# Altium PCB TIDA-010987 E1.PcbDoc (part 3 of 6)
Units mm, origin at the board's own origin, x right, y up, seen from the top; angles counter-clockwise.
Board outline 154.15 x 103.76 mm, 4 copper layers (5V, GND, MidSupply, -5V), stack 1.787 mm thick; 92 components, 52 nets, 1640 pads, 56 vias.
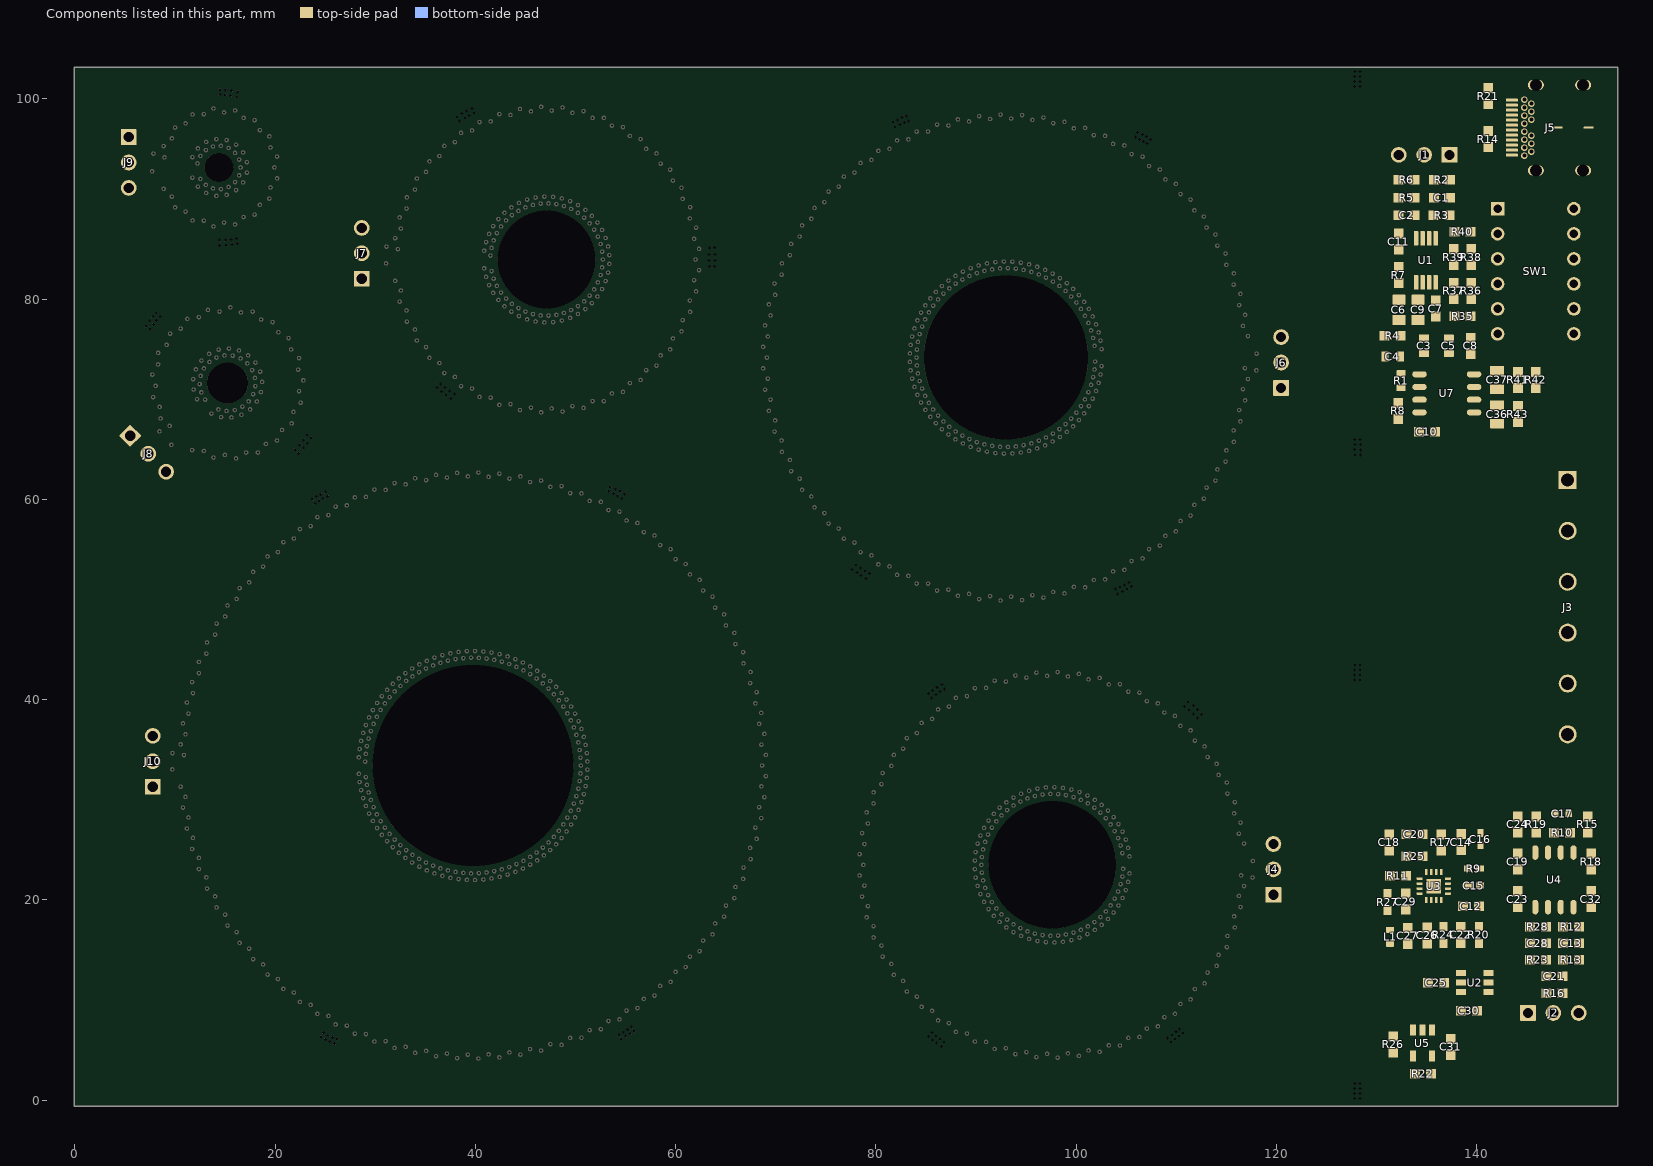
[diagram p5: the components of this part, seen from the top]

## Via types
v1: diameter 0.61, hole 0.203, 5V to -5V, tented both sides, 52 vias
v2: diameter 0.5, hole 0.2, 5V to -5V, tented both sides, 4 vias

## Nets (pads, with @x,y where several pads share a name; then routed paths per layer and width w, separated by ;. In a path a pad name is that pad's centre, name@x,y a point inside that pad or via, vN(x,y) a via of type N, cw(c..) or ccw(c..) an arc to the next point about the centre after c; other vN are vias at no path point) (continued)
copper on no net: (continued)
  5V w0.1: 5.38,66.208 6.209,66.949 8.426,66.825 8.461,66.786 ; 5.383,91.096 5.408,91.905 7.789,94.146 8.547,94.005 cw(c14.398,93.14) 8.883,95.276 ; 5.383,96.176 6.716,96.005 7.858,94.525 ; 7.667,93.134 ccw(c14.398,93.956) 7.724,92.755 ; 7.713,93.14 12.222,93.14 cw(c14.398,93.14) 12.259,93.539 ; 7.744,72.453 ccw(c15.261,71.606) 7.766,70.579 ccw(c7.828,70.199) 7.909,69.823 ccw(c15.261,71.606) 8.402,68.415 cw(c8.573,68.071) 8.913,68.251 12.211,69.994 ; 7.798,31.293 7.745,31.777 9.748,34.271 ; 7.828,70.199 11.872,70.964 ; 7.846,36.244 9.761,34.657 ; 8.086,71.337 12.095,71.487 cw(c12.48,71.501) 12.492,71.886 cw(c15.261,71.606) 12.499,71.948 ccw(c12.573,72.326) 12.698,72.69 cw(c15.261,71.606) 12.905,73.086 ; 8.326,73.464 12.573,72.326 ; 8.327,74.631 12.099,72.985 ; 8.484,69.234 12.634,70.686 ; 8.573,68.071 ccw(c15.261,71.606) 9.311,66.934 8.691,66.477 8.746,63.123 9.127,62.755 ; 8.883,91.003 11.747,92.113 ; 8.962,94.156 11.881,93.61 cw(c12.259,93.539) 12.363,93.91 cw(c14.398,93.14) 12.375,93.942 ccw(c12.548,94.285) 12.779,94.593 cw(c14.398,93.14) 13.087,94.876 ; 9.182,75.426 12.579,73.291 cw(c12.905,73.086) 13.132,73.397 cw(c15.261,71.606) 13.172,73.445 ccw(c13.446,73.715) 13.754,73.945 cw(c15.261,71.606) 14.148,74.156 ; 9.345,65.685 ccw(c14.727,72.14) 9.646,65.446 ; 9.368,65.712 13.293,69.638 cw(c15.261,71.606) 13.022,69.953 ; 9.484,67.342 12.712,69.724 cw(c13.022,69.953) 12.816,70.278 cw(c15.261,71.606) 12.786,70.333 ccw(c12.634,70.686) 12.533,71.057 cw(c15.261,71.606) 12.48,71.501 ; 9.527,76.54 ccw(c15.261,71.606) 8.49,74.98 ccw(c8.327,74.631) 8.183,74.274 ccw(c15.261,71.606) 7.797,72.834 cw(c7.744,72.453) 8.126,72.409 11.833,71.992 ; 9.697,90.228 12.548,91.994 ; 9.696,96.051 12.548,94.285 ; 9.73,33.412 ccw(c39.771,33.873) 9.738,33.027 ; 9.736,33.412 9.743,33.412 29.005,33.412 cw(c39.771,33.412) 29.012,33.801 ; 9.748,34.272 10.517,34.244 cw(c39.771,33.412) 10.582,35.524 ; 10.027,89.155 ccw(c14.398,93.14) 11.423,88.027 ccw(c11.762,87.845) 12.112,87.684 ccw(c14.398,93.14) 13.47,87.298 cw(c13.852,87.25) 13.888,87.633 14.136,90.309 ; 10.027,97.124 12.297,95.055 ; 10.578,77.048 13.446,73.715 ; 10.582,31.301 28.368,32.587 ; 10.81,29.2 ccw(c39.771,33.412) 11.11,27.498 ccw(c11.19,27.121) 11.275,26.746 ccw(c39.771,33.412) 11.611,25.445 cw(c11.718,25.075) 12.087,25.185 28.812,30.155 ; 10.81,37.625 28.457,35.058 ; 10.909,34.455 28.627,33.815 cw(c29.012,33.801) 29.032,34.185 cw(c39.771,33.412) 29.033,34.193 ccw(c29.068,34.576) 29.116,34.958 cw(c39.771,33.412) 29.18,35.346 ; 11.06,30.29 29.068,32.248 ; 11.06,36.535 29.068,34.576 ; 11.066,88.727 12.855,91.096 cw(c13.087,91.403) 12.802,91.661 cw(c14.398,93.14) 12.779,91.686 ccw(c12.548,91.994) 12.375,92.338 cw(c14.398,93.14) 12.259,92.74 8.584,92.053 ccw(c14.398,93.14) 8.755,91.366 ccw(c8.883,91.003) 9.033,90.649 ccw(c14.398,93.14) 9.777,89.447 cw(c10.027,89.155) 10.311,89.414 12.297,91.224 ; 11.066,97.553 12.855,95.183 cw(c13.087,94.876) 13.413,95.08 cw(c14.398,93.14) 13.444,95.095 ccw(c13.803,95.232) 14.18,95.305 cw(c14.398,93.14) 14.599,95.306 ; 11.19,27.121 28.605,30.955 ; 11.19,39.703 ccw(c39.771,33.412) 10.868,38.005 ccw(c10.81,37.625) 10.757,37.243 ccw(c39.771,33.412) 10.612,35.908 cw(c10.582,35.524) 10.966,35.496 28.368,34.237 ; 11.236,78.011 13.426,74.527 ; 11.36,28.226 28.801,31.41 cw(c29.18,31.479) 29.117,31.859 cw(c39.771,33.412) 29.116,31.866 ccw(c29.068,32.248) 29.033,32.632 cw(c39.771,33.412) 29.012,33.024 10.525,32.356 ccw(c39.771,33.412) 10.557,31.685 ccw(c10.582,31.301) 10.612,30.917 ccw(c39.771,33.412) 10.758,29.581 cw(c10.81,29.2) 11.191,29.255 28.457,31.767 ; 11.36,38.598 28.801,35.415 cw(c29.18,35.346) 29.256,35.723 cw(c39.771,33.412) 29.257,35.73 ccw(c29.347,36.105) 29.45,36.476 cw(c39.771,33.412) 29.568,36.85 ; 11.718,25.075 ccw(c39.771,33.412) 12.259,23.434 ccw(c12.393,23.073) 12.531,22.714 ccw(c39.771,33.412) 13.051,21.475 cw(c13.21,21.124) 13.56,21.286 29.395,28.612 ; 11.718,41.749 28.812,36.669 ; 11.726,64.917 13.649,68.555 ; 11.747,94.166 9.242,95.137 ccw(c8.883,95.276) 9.033,95.631 cw(c14.398,93.14) 9.777,96.832 cw(c10.027,97.124) 10.295,97.4 cw(c14.398,93.14) 11.762,98.434 ; 11.762,87.845 13.131,90.595 ; 11.808,26.19 29.347,30.72 ; 11.808,40.635 29.347,36.105 ; 12.39,78.186 13.994,74.509 ; 12.393,23.073 29.075,29.373 ; 12.393,43.752 ccw(c39.771,33.412) 11.83,42.118 ccw(c11.718,41.749) 11.611,41.38 ccw(c39.771,33.412) 11.275,40.079 cw(c11.19,39.703) 11.566,39.621 28.605,35.87 ; 12.402,24.191 29.203,29.852 cw(c29.568,29.975) 29.452,30.342 cw(c39.771,33.412) 29.45,30.349 ccw(c29.347,30.72) 29.257,31.094 cw(c39.771,33.412) 29.18,31.479 ; 12.402,42.634 29.203,36.973 cw(c29.568,36.85) 29.698,37.213 cw(c39.771,33.412) 29.7,37.22 ccw(c29.843,37.577) 29.998,37.929 cw(c39.771,33.412) 30.169,38.283 ; 12.646,73.856 9.819,76.289 ccw(c9.527,76.54) 9.786,76.825 cw(c15.261,71.606) 10.916,77.798 cw(c11.236,78.011) 11.568,78.207 cw(c15.261,71.606) 13.303,78.913 ; 12.885,87.821 13.803,91.047 ; 12.885,98.458 13.803,95.232 ; 12.89,64.828 14.342,68.979 ; 13.087,91.403 ccw(c14.398,93.14) 13.444,91.184 ; 13.131,95.684 11.933,98.09 ccw(c11.762,98.434) 12.112,98.595 cw(c14.398,93.14) 13.47,98.981 cw(c13.852,99.029) 14.237,99.052 cw(c14.398,93.14) 16.017,98.829 ; 13.139,22.24 29.843,29.248 ; 13.139,44.585 29.843,37.577 ; 13.21,21.124 ccw(c39.771,33.412) 13.982,19.578 ccw(c14.166,19.24) 14.355,18.904 ccw(c39.771,33.412) 15.048,17.753 cw(c15.256,17.429) 15.578,17.639 30.194,27.168 ; 13.21,45.7 29.395,38.213 ; 13.444,91.184 cw(c13.803,91.047) 14.18,90.974 ccw(c14.398,93.14) 14.214,90.971 ccw(c14.599,90.973) 14.634,90.59 ; 13.852,87.25 ccw(c14.398,93.14) 15.643,87.357 ccw(c16.017,87.45) 16.384,87.568 ccw(c14.398,93.14) 17.648,88.197 cw(c17.963,88.419) 17.731,88.726 16.111,90.871 ; 13.852,99.029 14.136,95.97 ; 13.855,64.172 ccw(c15.261,71.606) 15.725,64.055 ccw(c16.108,64.088) 16.49,64.141 ccw(c15.261,71.606) 17.93,64.527 cw(c18.286,64.672) 18.133,65.025 16.641,68.444 ; 13.995,74.509 cw(c14.148,74.156) 14.511,74.285 cw(c15.261,71.606) 14.571,74.302 ccw(c14.95,74.371) 15.334,74.388 cw(c15.261,71.606) 15.779,74.34 ; 14.015,20.348 29.826,28.368 cw(c30.169,28.542) 30.001,28.888 cw(c39.771,33.412) 29.998,28.895 ccw(c29.843,29.248) 29.7,29.605 cw(c39.771,33.412) 29.568,29.975 ; 14.015,46.477 29.826,38.457 cw(c30.169,38.283) 30.35,38.623 cw(c39.771,33.412) 30.353,38.629 ccw(c30.546,38.963) 30.75,39.289 cw(c39.771,33.412) 30.97,39.614 ; 14.166,19.24 29.768,27.876 ; 14.166,47.585 ccw(c39.771,33.412) 13.374,46.049 ccw(c13.21,45.7) 13.051,45.35 ccw(c39.771,33.412) 12.531,44.111 cw(c12.393,43.752) 12.753,43.616 29.075,37.452 ; 14.368,74.938 13.403,78.541 ccw(c13.303,78.913) 13.678,79.003 cw(c15.261,71.606) 15.159,79.17 cw(c15.544,79.165) 15.928,79.141 cw(c15.261,71.606) 17.76,78.746 ; 14.457,78.74 14.95,74.371 ; 14.599,90.973 ccw(c14.398,93.14) 15.01,91.051 cw(c15.368,91.192) 15.696,91.393 ccw(c14.398,93.14) 15.723,91.413 ccw(c16.006,91.674) 16.29,91.415 18.485,89.414 ; 14.62,68.216 13.926,64.551 ccw(c13.855,64.172) 13.479,64.254 cw(c15.261,71.606) 12.071,64.746 cw(c11.726,64.917) 11.391,65.106 cw(c15.261,71.606) 10.769,65.519 13.609,69.366 ccw(c15.261,71.606) 13.989,69.131 cw(c14.342,68.979) 14.713,68.877 ccw(c15.261,71.606) 14.775,68.865 ccw(c15.157,68.824) 15.143,68.44 14.993,64.431 ; 14.635,90.589 14.908,87.633 ; 14.908,98.646 14.634,95.69 cw(c14.599,95.306) 14.977,95.237 cw(c14.398,93.14) 15.01,95.228 ccw(c15.368,95.087) 15.696,94.886 cw(c14.398,93.14) 16.006,94.606 ; 15.025,18.523 30.546,27.862 ; 15.025,48.302 30.546,38.963 ; 15.157,68.824 ccw(c15.261,71.606) 15.604,68.844 cw(c15.982,68.917) 16.345,69.042 ccw(c15.261,71.606) 16.403,69.067 ccw(c16.742,69.249) 16.947,68.923 ; 15.176,90.405 16.017,87.45 ; 15.176,95.874 15.912,98.458 ccw(c16.017,98.829) 16.384,98.711 cw(c14.398,93.14) 17.648,98.082 cw(c17.963,97.86) 18.262,97.618 cw(c14.398,93.14) 19.427,96.253 ; 15.256,17.429 ccw(c39.771,33.412) 16.242,16.01 ccw(c16.473,15.702) 16.708,15.397 ccw(c39.771,33.412) 17.559,14.358 cw(c17.812,14.067) 18.101,14.321 31.192,25.855 ; 15.256,49.395 30.194,39.656 ; 15.368,95.087 16.863,98.09 ; 15.368,91.192 16.863,88.189 ; 15.39,75.053 15.544,79.165 ; 15.648,68.177 16.108,64.088 ; 15.982,68.917 17.12,64.67 ; 16.006,91.674 ccw(c14.398,93.14) 16.257,92.009 cw(c16.427,92.354) 16.534,92.723 ccw(c14.398,93.14) 16.54,92.757 ccw(c16.574,93.14) 16.959,93.14 19.928,93.14 ; 16.111,95.408 17.963,97.86 ; 16.164,16.776 30.656,26.989 cw(c30.97,27.211) 30.754,27.529 cw(c39.771,33.412) 30.75,27.536 ccw(c30.546,27.862) 30.353,28.195 cw(c39.771,33.412) 30.169,28.542 ; 16.164,50.048 30.656,39.836 cw(c30.97,39.614) 31.198,39.925 cw(c39.771,33.412) 31.202,39.931 ccw(c31.441,40.233) 31.69,40.526 cw(c39.771,33.412) 31.955,40.816 ; 16.29,94.865 cw(c16.006,94.606) 16.239,94.3 cw(c14.398,93.14) 16.257,94.27 ccw(c16.427,93.926) 16.534,93.556 cw(c14.398,93.14) 16.574,93.14 ; 16.291,94.865 18.485,96.865 ; 16.401,74.862 17.633,78.383 ccw(c17.76,78.746) 18.12,78.61 cw(c15.261,71.606) 19.438,77.913 cw(c19.754,77.692) 20.057,77.456 cw(c15.261,71.606) 21.348,76.098 ; 16.427,92.354 19.555,91.142 ; 16.427,93.926 19.555,95.137 ; 16.473,15.702 30.669,26.493 ; 16.473,51.123 ccw(c39.771,33.412) 15.468,49.717 ccw(c15.256,49.395) 15.048,49.072 ccw(c39.771,33.412) 14.355,47.92 cw(c14.166,47.585) 14.503,47.398 29.768,38.949 ; 16.562,74.066 18.616,77.953 ; 16.596,78.66 15.85,74.718 cw(c15.779,74.34) 16.151,74.243 cw(c15.261,71.606) 16.21,74.222 ccw(c16.562,74.066) 16.889,73.863 cw(c15.261,71.606) 17.229,73.573 ; 16.742,69.249 ccw(c15.261,71.606) 17.1,69.517 cw(c17.371,69.79) 17.601,70.098 ccw(c15.261,71.606) 17.634,70.152 ccw(c17.812,70.493) 18.165,70.339 21.842,68.734 ; 16.815,91.643 19.427,90.026 ; 16.815,94.636 19.1,96.051 ; 16.947,68.923 19.081,65.526 ; 17.193,92.617 19.834,92.123 ccw(c20.212,92.053) 20.129,91.677 cw(c14.398,93.14) 19.619,90.359 cw(c19.427,90.026) 19.214,89.705 cw(c14.398,93.14) 17.963,88.419 ; 17.193,93.662 20.212,94.226 ; 17.31,74.381 19.754,77.692 ; 17.371,69.79 20.704,66.922 ; 17.425,15.116 31.441,26.592 ; 17.425,51.708 31.441,40.233 ; 17.512,68.991 20.196,65.871 ; 17.722,72.906 21.609,74.961 ; 17.812,14.067 ccw(c39.771,33.412) 18.992,12.804 ccw(c19.265,12.533) 19.541,12.265 ccw(c39.771,33.412) 20.533,11.359 cw(c20.825,11.108) 21.074,11.401 32.369,24.699 ; 17.812,52.758 31.192,40.97 ; 17.812,70.493 ccw(c15.261,71.606) 17.957,70.916 cw(c18.027,71.294) 18.043,71.678 ccw(c15.261,71.606) 18.041,71.741 ccw(c17.996,72.123) 18.374,72.194 22.316,72.94 ; 17.996,72.123 ccw(c15.261,71.606) 17.878,72.554 cw(c17.722,72.906) 17.519,73.233 ccw(c15.261,71.606) 17.482,73.283 ccw(c17.229,73.573) 17.501,73.845 20.338,76.683 ; 18.027,71.294 22.396,70.802 ; 18.037,73.654 21.038,75.869 ccw(c21.348,76.098) 21.569,75.782 cw(c15.261,71.606) 22.265,74.464 cw(c22.402,74.104) 22.52,73.738 cw(c15.261,71.606) 22.821,71.888 ; 18.182,69.77 21.341,67.786 ccw(c21.667,67.581) 21.454,67.26 cw(c15.261,71.606) 20.481,66.13 cw(c20.196,65.871) 19.898,65.628 cw(c15.261,71.606) 18.286,64.672 ; 18.518,72.745 22.402,74.104 ; 18.594,70.713 22.568,69.648 ; 18.709,71.735 22.436,71.874 ccw(c22.821,71.888) 22.826,71.503 cw(c15.261,71.606) 22.659,70.022 cw(c22.568,69.648) 22.459,69.278 cw(c15.261,71.606) 21.667,67.581 ; 18.804,13.552 31.675,25.744 cw(c31.955,26.009) 31.695,26.293 cw(c39.771,33.412) 31.69,26.298 ccw(c31.441,26.592) 31.202,26.894 cw(c39.771,33.412) 30.97,27.211 ; 18.804,53.273 31.675,41.081 cw(c31.955,40.816) 32.224,41.091 cw(c39.771,33.412) 32.23,41.096 ccw(c32.509,41.361) 32.798,41.615 cw(c39.771,33.412) 33.102,41.864 ; 19.1,96.051 ccw(c19.427,96.253) 19.619,95.92 cw(c14.398,93.14) 20.129,94.602 cw(c20.212,94.226) 20.271,93.846 cw(c14.398,93.14) 20.212,92.053 ; 19.265,12.533 31.76,25.255 ; 19.265,54.292 ccw(c39.771,33.412) 18.068,53.045 ccw(c17.812,52.758) 17.559,52.467 ccw(c39.771,33.412) 16.708,51.428 cw(c16.473,51.123) 16.779,50.89 30.669,40.331 ; 20.292,12.09 32.509,25.464 ; 20.292,54.734 32.509,41.361 ; 20.825,11.108 ccw(c39.771,33.412) 22.175,10.028 ccw(c22.484,9.799) 22.796,9.573 ccw(c39.771,33.412) 23.908,8.819 cw(c24.233,8.613) 24.437,8.939 33.701,23.724 ; 20.825,55.717 32.369,42.126 ; 21.881,10.74 32.863,24.658 cw(c33.102,24.961) 32.804,25.204 cw(c39.771,33.412) 32.798,25.209 ccw(c32.509,25.464) 32.23,25.729 cw(c39.771,33.412) 31.955,26.009 ; 21.881,56.084 32.863,42.166 cw(c33.102,41.864) 33.408,42.097 cw(c39.771,33.412) 33.414,42.102 ccw(c33.729,42.323) 34.051,42.534 cw(c39.771,33.412) 34.388,42.736 ; 22.484,9.799 33.017,24.187 ; 22.484,57.026 ccw(c39.771,33.412) 21.12,55.964 ccw(c20.825,55.717) 20.533,55.466 ccw(c39.771,33.412) 19.541,54.56 cw(c19.265,54.292) 19.535,54.017 31.76,41.569 ; 23.564,9.509 33.729,24.501 ; 23.564,57.316 33.729,42.323 ; 24.233,8.613 ccw(c39.771,33.412) 25.724,7.739 ccw(c26.063,7.556) 26.404,7.378 ccw(c39.771,33.412) 27.613,6.792 cw(c27.964,6.635) 28.119,6.987 35.158,22.951 ; 24.233,58.212 33.701,43.101 ; 25.331,8.402 34.195,23.755 cw(c34.388,24.089) 34.058,24.287 cw(c39.771,33.412) 34.051,24.291 ccw(c33.729,24.501) 33.414,24.723 cw(c39.771,33.412) 33.102,24.961 ; 25.331,58.423 34.195,43.069 cw(c34.388,42.736) 34.724,42.922 cw(c39.771,33.412) 34.731,42.926 ccw(c35.074,43.1) 35.424,43.262 cw(c39.771,33.412) 35.786,43.414 ; 26.063,7.556 34.415,23.311 ; 26.063,59.268 ccw(c39.771,33.412) 24.56,58.414 ccw(c24.233,58.212) 23.908,58.005 ccw(c39.771,33.412) 22.796,57.251 cw(c22.484,57.026) 22.711,56.715 33.017,42.637 ; 27.173,7.425 35.074,23.725 ; 27.173,59.4 35.074,43.1 ; 27.964,6.635 ccw(c39.771,33.412) 29.565,5.984 ccw(c29.927,5.852) 30.291,5.725 ccw(c39.771,33.412) 31.571,5.319 cw(c31.941,5.214) 32.044,5.585 36.712,22.396 ; 27.964,60.19 35.158,43.873 ; 28.661,82.022 31.107,84.841 31.875,84.787 cw(c47.117,83.947) 32.001,86.071 ; 28.832,87.274 31.055,85.222 31.133,85.225 ; 29.081,6.583 35.643,23.053 cw(c35.786,23.411) 35.431,23.56 cw(c39.771,33.412) 35.424,23.563 ccw(c35.074,23.725) 34.731,23.899 cw(c39.771,33.412) 34.388,24.089 ; 29.081,60.241 35.643,43.771 cw(c35.786,43.414) 36.146,43.55 cw(c39.771,33.412) 36.153,43.552 ccw(c36.518,43.675) 36.887,43.785 cw(c39.771,33.412) 37.267,43.883 ; 29.927,5.852 35.925,22.646 ; 29.927,60.972 ccw(c39.771,33.412) 28.317,60.343 ccw(c27.964,60.19) 27.613,60.032 ccw(c39.771,33.412) 26.404,59.446 cw(c26.063,59.268) 26.243,58.928 34.415,43.513 ; 31.045,5.882 36.518,23.15 ; 31.045,60.943 36.518,43.675 ; 31.069,83.947 ccw(c47.117,84.488) 31.087,83.562 ; 31.082,83.947 41.501,83.947 cw(c47.117,83.947) 41.515,84.339 ; 31.941,5.214 ccw(c39.771,33.412) 33.62,4.801 ccw(c33.997,4.723) 34.374,4.649 ccw(c39.771,33.412) 35.7,4.432 cw(c36.082,4.381) 36.13,4.763 38.33,22.071 ; 31.941,61.611 36.712,44.428 ; 32.001,81.823 40.896,83.073 ; 32.273,84.985 41.131,84.366 cw(c41.515,84.339) 41.555,84.722 cw(c47.117,83.947) 41.557,84.736 ccw(c41.624,85.115) 41.717,85.488 cw(c47.117,83.947) 41.84,85.868 ; 32.443,79.739 ccw(c47.117,83.947) 33.02,78.092 ccw(c33.172,77.738) 33.333,77.388 ccw(c47.117,83.947) 33.972,76.187 cw(c34.172,75.858) 34.498,76.062 41.789,80.618 ; 32.443,88.155 41.078,85.679 ; 32.562,80.853 41.624,82.779 ; 32.562,87.041 41.624,85.115 ; 33.054,5.324 37.177,22.567 cw(c37.267,22.942) 36.894,23.038 cw(c39.771,33.412) 36.887,23.04 ccw(c36.518,23.15) 36.153,23.272 cw(c39.771,33.412) 35.786,23.411 ; 33.054,61.5 37.177,44.258 cw(c37.267,43.883) 37.643,43.966 cw(c39.771,33.412) 37.65,43.967 ccw(c38.029,44.036) 38.41,44.092 cw(c39.771,33.412) 38.8,44.134 ; 33.134,78.858 41.478,81.895 cw(c41.84,82.026) 41.721,82.392 cw(c47.117,83.947) 41.717,82.406 ccw(c41.624,82.779) 41.557,83.158 cw(c47.117,83.947) 41.515,83.555 31.889,82.882 ccw(c47.117,83.947) 31.952,82.204 ccw(c32.001,81.823) 32.059,81.442 ccw(c47.117,83.947) 32.342,80.111 cw(c32.443,79.739) 32.813,79.846 41.078,82.215 ; 33.134,89.036 41.478,85.999 cw(c41.84,85.868) 41.984,86.225 cw(c47.117,83.947) 41.99,86.238 ccw(c42.159,86.583) 42.351,86.917 cw(c47.117,83.947) 42.574,87.248 ; 33.172,77.738 41.378,81.392 ; 33.172,90.156 ccw(c47.117,83.947) 32.554,88.523 ccw(c32.443,88.155) 32.342,87.783 ccw(c47.117,83.947) 32.059,86.452 cw(c32.001,86.071) 32.382,86.018 40.896,84.821 ; 33.979,76.961 42.159,81.311 ; 33.979,90.933 42.159,86.583 ; 33.997,4.723 37.515,22.204 ; 33.997,62.102 ccw(c39.771,33.412) 32.313,61.711 ccw(c31.941,61.611) 31.571,61.505 ccw(c39.771,33.412) 30.291,61.099 cw(c29.927,60.972) 30.057,60.61 35.925,44.179 ; 34.172,75.858 ccw(c47.117,83.947) 35.18,74.433 ccw(c35.423,74.135) 35.674,73.843 ccw(c47.117,83.947) 36.62,72.864 cw(c36.903,72.603) 37.16,72.889 42.913,79.278 ; 34.172,92.036 41.789,87.276 ; 35.079,75.201 42.262,80.42 cw(c42.574,80.646) 42.358,80.965 cw(c47.117,83.947) 42.351,80.977 ccw(c42.159,81.311) 41.99,81.656 cw(c47.117,83.947) 41.84,82.026 ; 35.079,92.693 42.262,87.474 cw(c42.574,87.248) 42.811,87.551 cw(c47.117,83.947) 42.82,87.562 ccw(c43.077,87.848) 43.354,88.116 cw(c47.117,83.947) 43.66,88.372 ; 35.098,4.913 38.029,22.788 ; 35.098,61.912 38.029,44.036 ; 35.423,74.135 42.304,79.909 ; 35.423,93.759 ccw(c47.117,83.947) 34.38,92.36 ccw(c34.172,92.036) 33.972,91.707 ccw(c47.117,83.947) 33.333,90.506 cw(c33.172,90.156) 33.523,89.999 41.378,86.502 ; 36.082,4.381 ccw(c39.771,33.412) 37.802,4.214 ccw(c38.186,4.19) 38.571,4.172 ccw(c39.771,33.412) 39.914,4.148 cw(c40.299,4.152) 40.292,4.537 39.977,21.981 ; 36.082,62.444 38.33,44.754 ; 36.413,73.61 43.077,80.046 ; 36.413,94.284 43.077,87.848 ; 36.903,72.603 ccw(c47.117,83.947) 38.264,71.511 ccw(c38.581,71.292) 38.903,71.081 ccw(c47.117,83.947) 40.081,70.4 cw(c40.425,70.227) 40.594,70.573 44.363,78.3 ; 36.903,95.291 42.913,88.616 ; 37.167,4.65 38.765,22.307 cw(c38.8,22.69) 38.417,22.732 cw(c39.771,33.412) 38.41,22.733 ccw(c38.029,22.788) 37.65,22.857 cw(c39.771,33.412) 37.267,22.942 ; 37.167,62.175 38.765,44.518 cw(c38.8,44.134) 39.184,44.162 cw(c39.771,33.412) 39.192,44.163 ccw(c39.576,44.177) 39.961,44.177 cw(c39.771,33.412) 40.354,44.163 ; 37.515,44.62 34.073,61.725 ccw(c33.997,62.102) 34.374,62.176 cw(c39.771,33.412) 35.7,62.393 cw(c36.082,62.444) 36.464,62.49 cw(c39.771,33.412) 38.186,62.634 ; 37.956,72.221 43.423,79.218 cw(c43.66,79.522) 43.365,79.769 cw(c47.117,83.947) 43.354,79.778 ccw(c43.077,80.046) 42.82,80.332 cw(c47.117,83.947) 42.574,80.646 ; 37.956,95.673 43.423,88.676 cw(c43.66,88.372) 43.971,88.599 cw(c47.117,83.947) 43.983,88.607 ccw(c44.309,88.81) 44.649,88.991 cw(c47.117,83.947) 45.013,89.154 ; 38.186,4.19 39.152,21.996 ; 38.581,71.292 43.604,78.739 ; 38.581,96.602 ccw(c47.117,83.947) 37.192,95.545 ccw(c36.903,95.291) 36.62,95.03 ccw(c47.117,83.947) 35.674,94.051 cw(c35.423,93.759) 35.718,93.512 42.304,87.985 ; 38.8,22.69 ccw(c39.771,33.412) 39.192,22.662 cw(c39.576,22.648) 39.961,22.648 ccw(c39.771,33.412) 39.969,22.648 ccw(c40.354,22.662) 40.374,22.278 ; 39.152,44.828 38.207,62.25 ccw(c38.186,62.634) 38.571,62.653 cw(c39.771,33.412) 39.914,62.677 cw(c40.299,62.673) 40.684,62.663 cw(c39.771,33.412) 42.409,62.558 ; 39.249,4.537 39.576,22.648 ; 39.249,62.288 39.576,44.177 ; 39.677,71.061 44.309,79.084 ; 39.677,96.833 44.309,88.81 ; 39.977,44.843 40.299,62.673 ; 40.299,4.152 ccw(c39.771,33.412) 42.025,4.234 ccw(c42.409,4.266) 42.792,4.304 ccw(c39.771,33.412) 44.125,4.473 cw(c44.505,4.533) 44.443,4.913 41.62,22.13 ; 40.354,22.662 ccw(c39.771,33.412) 40.745,22.691 cw(c41.128,22.732) 41.509,22.788 ccw(c39.771,33.412) 41.516,22.789 ccw(c41.895,22.858) 41.971,22.481 45.469,5.1 ; 40.374,22.278 41.334,4.575 ; 40.425,70.227 ccw(c47.117,83.947) 42.035,69.553 ccw(c42.4,69.429) 42.767,69.315 ccw(c47.117,83.947) 44.088,68.986 cw(c44.466,68.914) 44.533,69.293 46.026,77.76 ; 40.425,97.667 44.363,89.594 ; 40.801,22.026 42.409,4.266 ; 40.801,44.799 42.374,62.175 ccw(c42.409,62.558) 42.792,62.521 cw(c39.771,33.412) 44.125,62.352 cw(c44.505,62.292) 44.885,62.227 cw(c39.771,33.412) 46.577,61.875 ; 41.128,22.732 43.411,4.763 ; 41.128,44.092 43.411,62.062 ; 41.334,62.25 40.374,44.547 cw(c40.354,44.163) 40.737,44.135 cw(c39.771,33.412) 40.745,44.134 ccw(c41.128,44.092) 41.509,44.037 cw(c39.771,33.412) 41.895,43.967 ; 41.543,70.151 44.869,78.383 cw(c45.013,78.74) 44.662,78.897 cw(c47.117,83.947) 44.649,78.903 ccw(c44.309,79.084) 43.983,79.287 cw(c47.117,83.947) 43.66,79.522 ; 41.543,97.743 44.869,89.511 cw(c45.013,89.154) 45.375,89.286 cw(c47.117,83.947) 45.388,89.29 ccw(c45.758,89.396) 46.135,89.476 cw(c47.117,83.947) 46.53,89.532 ; 41.62,44.695 44.505,62.292 ; 41.895,22.858 ccw(c39.771,33.412) 42.278,22.942 cw(c42.651,23.039) 43.02,23.148 ccw(c39.771,33.412) 43.027,23.151 ccw(c43.392,23.274) 43.521,22.911 49.485,6.215 ; 42.4,69.429 45.176,77.972 ; 42.4,98.465 ccw(c47.117,83.947) 40.773,97.831 ccw(c40.425,97.667) 40.081,97.494 ccw(c47.117,83.947) 38.903,96.813 cw(c38.581,96.602) 38.796,96.283 43.604,89.155 ; 42.43,22.293 46.577,4.95 ; 42.43,44.532 46.487,61.5 ccw(c46.577,61.875) 46.951,61.783 cw(c39.771,33.412) 48.245,61.423 cw(c48.613,61.31) 48.979,61.191 cw(c39.771,33.412) 50.603,60.599 ; 42.651,23.039 47.497,5.585 ; 42.651,43.786 47.497,61.24 ; 43.225,22.514 48.496,5.882 ccw(c48.613,5.515) 48.245,5.401 cw(c39.771,33.412) 46.951,5.042 cw(c46.577,4.95) 46.202,4.863 cw(c39.771,33.412) 44.505,4.533 ; 43.225,44.311 48.613,61.31 ; 43.392,23.274 ccw(c39.771,33.412) 43.759,23.412 cw(c44.114,23.561) 44.463,23.723 ccw(c39.771,33.412) 44.47,23.726 ccw(c44.814,23.9) 44.994,23.56 53.298,7.897 ; 43.392,43.551 ccw(c39.771,33.412) 43.02,43.676 cw(c42.651,43.786) 42.278,43.882 ccw(c39.771,33.412) 42.271,43.884 ccw(c41.895,43.967) 41.971,44.344 45.469,61.725 ; 43.517,69.509 45.758,78.498 ; 43.517,98.385 45.758,89.396 ; 44.002,22.791 50.603,6.226 ; 44.002,44.033 50.46,60.241 ccw(c50.603,60.599) 50.959,60.454 cw(c39.771,33.412) 52.189,59.912 cw(c52.536,59.746) 52.882,59.576 cw(c39.771,33.412) 54.403,58.757 ; 44.114,23.561 51.422,6.987 ; 44.114,43.263 51.422,59.838 ; 44.466,68.914 ccw(c47.117,83.947) 46.2,68.71 ccw(c46.584,68.691) 46.969,68.683 ccw(c47.117,83.947) 48.329,68.73 cw(c48.713,68.766) 48.672,69.149 47.774,77.699 ; 44.466,98.98 46.026,90.134 ; 44.758,23.125 52.368,7.425 ccw(c52.536,7.078) 52.189,6.913 cw(c39.771,33.412) 50.959,6.371 cw(c50.603,6.226) 50.244,6.086 cw(c39.771,33.412) 48.613,5.515 ; 44.758,43.7 52.536,59.746 ; 44.814,23.9 ccw(c39.771,33.412) 45.157,24.091 cw(c45.487,24.289) 45.809,24.499 ccw(c39.771,33.412) 45.816,24.504 ccw(c46.13,24.725) 46.358,24.415 56.83,10.109 ; 44.814,42.924 ccw(c39.771,33.412) 44.463,43.102 cw(c44.114,43.263) 43.759,43.412 ccw(c39.771,33.412) 43.752,43.415 ccw(c43.392,43.551) 43.521,43.914 49.485,60.61 ; 45.013,78.74 ccw(c47.117,83.947) 45.388,78.604 cw(c45.758,78.498) 46.135,78.418 ccw(c47.117,83.947) 46.149,78.415 ccw(c46.53,78.362) 46.49,77.979 45.562,69.149 ; 45.176,89.922 42.519,98.099 ccw(c42.4,98.465) 42.767,98.579 cw(c47.117,83.947) 44.088,98.908 cw(c44.466,98.98) 44.846,99.042 cw(c47.117,83.947) 46.584,99.203 ; 45.487,23.511 54.403,8.068 ; 45.487,24.289 55.104,8.939 ; 45.487,42.536 55.104,57.886 ; 45.487,43.313 54.211,58.423 ccw(c54.403,58.757) 54.735,58.562 cw(c39.771,33.412) 55.874,57.849 cw(c56.194,57.635) 56.511,57.417 cw(c39.771,33.412) 57.899,56.386 ; 45.562,98.745 46.49,89.915 cw(c46.53,89.532) 46.914,89.559 cw(c47.117,83.947) 46.928,89.559 ccw(c47.313,89.559) 47.697,89.533 cw(c47.117,83.947) 48.092,89.477 ; 46.13,24.725 ccw(c39.771,33.412) 46.443,24.963 cw(c46.74,25.207) 47.029,25.461 ccw(c39.771,33.412) 47.035,25.466 ccw(c47.314,25.731) 47.584,25.457 60.007,12.808 ; 46.13,42.099 ccw(c39.771,33.412) 45.809,42.325 cw(c45.487,42.536) 45.157,42.734 ccw(c39.771,33.412) 45.15,42.738 ccw(c44.814,42.924) 44.994,43.264 53.298,58.928 ; 46.187,23.95 55.978,9.509 ccw(c56.194,9.19) 55.874,8.976 cw(c39.771,33.412) 54.735,8.263 cw(c54.403,8.068) 54.068,7.878 cw(c39.771,33.412) 52.536,7.078 ; 46.187,42.875 56.194,57.635 ; 46.53,78.362 ccw(c47.117,83.947) 46.928,78.335 cw(c47.313,78.335) 47.697,78.361 ccw(c47.117,83.947) 47.711,78.363 ccw(c48.092,78.417) 48.159,78.038 49.701,69.293 ; 46.584,68.691 46.898,77.668 ; 46.74,25.207 58.467,11.401 ; 46.74,41.618 58.467,55.424 ; 46.853,24.437 57.899,10.438 ; 46.853,42.388 57.66,56.084 ccw(c57.899,56.386) 58.199,56.146 cw(c39.771,33.412) 59.223,55.276 cw(c59.509,55.018) 59.792,54.757 cw(c39.771,33.412) 61.017,53.538 ; 46.898,90.226 46.598,98.818 ccw(c46.584,99.203) 46.969,99.211 cw(c47.117,83.947) 48.329,99.164 cw(c48.713,99.128) 49.095,99.083 cw(c47.117,83.947) 50.81,98.759 ; 47.313,78.335 47.636,69.076 ; 47.313,89.559 47.636,98.818 ; 47.314,25.731 ccw(c39.771,33.412) 47.589,26.011 cw(c47.849,26.296) 48.098,26.589 ccw(c39.771,33.412) 48.103,26.595 ccw(c48.341,26.897) 48.648,26.664 62.762,15.935 ; 47.314,41.093 ccw(c39.771,33.412) 47.029,41.363 cw(c46.74,41.618) 46.443,41.862 ccw(c39.771,33.412) 46.437,41.866 ccw(c46.13,42.099) 46.358,42.41 56.83,56.715 ; 47.482,24.972 59.25,12.09 ccw(c59.509,11.806) 59.223,11.548 cw(c39.771,33.412) 58.199,10.679 cw(c57.899,10.438) 57.595,10.202 cw(c39.771,33.412) 56.194,9.19 ; 47.482,41.853 59.509,55.018 ; 47.774,90.195 48.713,99.128 ; 47.849,26.296 61.441,14.321 ; 47.849,40.529 61.441,52.503 ; 48.071,25.55 61.017,13.287 ; 48.071,41.275 60.737,53.273 ccw(c61.017,53.538) 61.28,53.257 cw(c39.771,33.412) 62.168,52.249 cw(c62.414,51.952) 62.656,51.653 cw(c39.771,33.412) 63.693,50.27 ; 48.092,78.417 ccw(c47.117,83.947) 48.482,78.5 cw(c48.852,78.606) 49.214,78.738 ccw(c47.117,83.947) 49.227,78.743 ccw(c49.579,78.9) 49.747,78.554 53.64,70.573 ; 48.341,26.897 ccw(c39.771,33.412) 48.573,27.214 cw(c48.789,27.532) 48.994,27.859 ccw(c39.771,33.412) 48.998,27.865 ccw(c49.19,28.199) 49.527,28.012 65.038,19.426 ; 48.341,39.928 ccw(c39.771,33.412) 48.098,40.236 cw(c47.849,40.529) 47.589,40.813 ccw(c39.771,33.412) 47.584,40.819 ccw(c47.314,41.093) 47.584,41.368 60.007,54.017 ; 48.617,26.169 62.116,15.116 ccw(c62.414,14.872) 62.168,14.576 cw(c39.771,33.412) 61.28,13.568 cw(c61.017,13.287) 60.75,13.009 cw(c39.771,33.412) 59.509,11.806 ; 48.617,40.655 62.414,51.952 ; 48.637,77.851 50.81,69.135 ; 48.637,90.043 50.717,98.385 ccw(c50.81,98.759) 51.182,98.661 cw(c47.117,83.947) 52.477,98.24 cw(c52.835,98.1) 53.19,97.952 cw(c47.117,83.947) 54.75,97.167 ; 48.713,68.766 ccw(c47.117,83.947) 50.435,69.047 ccw(c50.81,69.135) 51.182,69.233 ccw(c47.117,83.947) 52.477,69.654 cw(c52.835,69.794) 52.691,70.15 49.47,78.122 ; 48.789,27.532 63.963,17.639 ; 48.789,39.292 63.963,49.185 ; 48.852,78.606 51.715,69.795 ; 48.852,89.288 51.715,98.099 ; 49.116,26.827 63.693,16.555 ; 49.116,39.998 63.378,50.048 ccw(c63.693,50.27) 63.912,49.954 cw(c39.771,33.412) 64.646,48.829 cw(c64.847,48.5) 65.043,48.169 cw(c39.771,33.412) 65.87,46.651 ; 49.19,28.199 ccw(c39.771,33.412) 49.374,28.545 cw(c49.542,28.892) 49.697,29.244 ccw(c39.771,33.412) 49.7,29.251 ccw(c49.842,29.609) 50.202,29.473 66.788,23.209 ; 49.19,38.626 ccw(c39.771,33.412) 48.994,38.966 cw(c48.789,39.292) 48.573,39.611 ccw(c39.771,33.412) 48.569,39.617 ccw(c48.341,39.928) 48.648,40.161 62.762,50.89 ; 49.47,89.772 52.835,98.1 ; 49.542,28.892 65.981,21.286 ; 49.542,37.933 65.981,45.539 ; 49.567,27.518 64.517,18.523 ccw(c64.847,18.325) 64.646,17.996 cw(c39.771,33.412) 63.912,16.871 cw(c63.693,16.555) 63.469,16.241 cw(c39.771,33.412) 62.414,14.872 ; 49.567,39.307 64.847,48.5 ; 49.579,78.9 ccw(c47.117,83.947) 49.931,79.087 cw(c50.257,79.291) 50.569,79.517 ccw(c47.117,83.947) 50.58,79.526 ccw(c50.875,79.774) 51.132,79.488 57.074,72.889 ; 49.579,88.994 ccw(c47.117,83.947) 49.214,89.156 cw(c48.852,89.288) 48.482,89.394 ccw(c47.117,83.947) 48.469,89.398 ccw(c48.092,89.477) 48.159,89.856 49.701,98.601 ; 49.842,29.609 ccw(c39.771,33.412) 49.974,29.978 cw(c50.091,30.345) 50.194,30.716 ccw(c39.771,33.412) 50.195,30.724 ccw(c50.285,31.098) 50.661,31.015 67.975,27.204 ; 49.842,37.216 ccw(c39.771,33.412) 49.697,37.581 cw(c49.542,37.933) 49.374,38.279 ccw(c39.771,33.412) 49.37,38.286 ccw(c49.19,38.626) 49.527,38.813 65.038,47.398 ; 49.967,28.24 65.87,20.173 ; 49.967,38.584 65.527,46.477 ccw(c65.87,46.651) 66.042,46.307 cw(c39.771,33.412) 66.606,45.088 cw(c66.757,44.733) 66.904,44.377 cw(c39.771,33.412) 67.504,42.757 ; 50.091,30.345 67.454,25.185 ; 50.091,36.479 67.454,41.64 ; 50.257,79.291 55.438,71.611 ; 50.257,88.603 55.438,96.283 ; 50.258,78.506 54.749,70.727 ; 50.258,89.388 54.557,96.833 ccw(c54.749,97.167) 55.08,96.97 cw(c47.117,83.947) 56.209,96.209 cw(c56.515,95.976) 56.815,95.735 cw(c47.117,83.947) 58.098,94.551 ; 50.285,31.098 ccw(c39.771,33.412) 50.362,31.483 cw(c50.425,31.863) 50.473,32.245 ccw(c39.771,33.412) 50.474,32.252 ccw(c50.509,32.635) 50.893,32.608 ; 50.285,35.727 ccw(c39.771,33.412) 50.194,36.108 cw(c50.091,36.479) 49.974,36.846 ccw(c39.771,33.412) 49.972,36.853 ccw(c49.842,37.216) 50.202,37.352 66.788,43.616 ; 50.313,28.99 66.402,22.24 ccw(c66.757,22.091) 66.606,21.737 cw(c39.771,33.412) 66.042,20.518 cw(c65.87,20.173) 65.693,19.831 cw(c39.771,33.412) 64.847,18.325 ; 50.313,37.835 66.757,44.733 ; 50.425,31.863 68.35,29.255 ; 50.425,34.962 68.35,37.569 ; 50.509,32.635 ccw(c39.771,33.412) 50.53,33.027 cw(c50.537,33.412) 50.53,33.797 ccw(c39.771,33.412) 50.529,33.805 ccw(c50.509,34.189) 50.893,34.217 ; 50.509,34.189 ccw(c39.771,33.412) 50.473,34.58 cw(c50.425,34.962) 50.362,35.342 ccw(c39.771,33.412) 50.361,35.349 ccw(c50.285,35.727) 50.661,35.809 67.975,39.621 ; 50.537,33.412 68.651,33.412 ; 50.605,29.762 67.504,24.068 ; 50.605,37.063 67.139,42.634 ccw(c67.504,42.757) 67.624,42.391 cw(c39.771,33.412) 68.007,41.103 cw(c68.106,40.731) 68.2,40.358 cw(c39.771,33.412) 68.56,38.668 ; 50.84,30.553 67.733,26.19 ccw(c68.106,26.093) 68.007,25.721 cw(c39.771,33.412) 67.624,24.434 cw(c67.504,24.068) 67.378,23.704 cw(c39.771,33.412) 66.757,22.091 ; 50.84,36.272 68.106,40.731 ; 50.875,79.774 ccw(c47.117,83.947) 51.161,80.051 cw(c51.419,80.337) 51.656,80.64 ccw(c47.117,83.947) 51.664,80.652 ccw(c51.879,80.971) 52.206,80.767 59.736,76.062 ; 50.875,88.12 ccw(c47.117,83.947) 50.569,88.377 cw(c50.257,88.603) 49.931,88.807 ccw(c47.117,83.947) 49.919,88.814 ccw(c49.579,88.994) 49.747,89.34 53.64,97.321 ; 50.893,32.608 68.575,31.328 ; 50.893,34.217 68.575,35.496 ; 50.985,78.996 56.278,72.221 ccw(c56.515,71.918) 56.209,71.685 cw(c47.117,83.947) 55.08,70.924 cw(c54.749,70.727) 54.414,70.539 cw(c47.117,83.947) 52.835,69.794 ; 50.985,88.898 56.515,95.976 ; 51.018,31.359 68.56,28.157 ; 51.018,35.465 68.181,38.598 ccw(c68.56,38.668) 68.627,38.288 cw(c39.771,33.412) 68.82,36.959 cw(c68.864,36.576) 68.903,36.193 cw(c39.771,33.412) 69.017,34.469 ; 51.136,32.176 68.481,30.29 ccw(c68.864,30.248) 68.82,29.866 cw(c39.771,33.412) 68.627,28.536 cw(c68.56,28.157) 68.488,27.779 cw(c39.771,33.412) 68.106,26.093 ; 51.136,34.648 68.864,36.576 ; 51.196,33 69.017,32.356 ; 51.196,33.825 68.632,34.455 ccw(c69.017,34.469) 69.028,34.084 cw(c39.771,33.412) 69.028,32.741 cw(c69.017,32.356) 69,31.971 cw(c39.771,33.412) 68.864,30.248 ; 51.419,80.337 58.516,74.382 ; 51.419,87.557 58.516,93.512 ; 51.636,79.583 58.098,73.343 ; 51.636,88.311 57.821,94.284 ccw(c58.098,94.551) 58.362,94.271 cw(c47.117,83.947) 59.236,93.228 cw(c59.467,92.92) 59.689,92.605 cw(c47.117,83.947) 60.595,91.113 ; 51.879,80.971 ccw(c47.117,83.947) 52.079,81.317 cw(c52.247,81.663) 52.392,82.02 ccw(c47.117,83.947) 52.396,82.033 ccw(c52.515,82.399) 52.885,82.293 ; 51.879,86.923 ccw(c47.117,83.947) 51.656,87.254 cw(c51.419,87.557) 51.161,87.843 ccw(c47.117,83.947) 51.152,87.853 ccw(c50.875,88.12) 51.132,88.406 57.074,95.005 ; 52.2,80.254 59.155,75.201 ccw(c59.467,74.974) 59.236,74.666 cw(c47.117,83.947) 58.362,73.623 cw(c58.098,73.343) 57.827,73.069 cw(c47.117,83.947) 56.515,71.918 ; 52.2,87.64 59.467,92.92 ; 52.247,81.663 60.711,77.895 ; 52.247,86.231 60.711,89.999 ; 52.515,82.399 ccw(c47.117,83.947) 52.611,82.786 cw(c52.678,83.165) 52.719,83.548 ccw(c47.117,83.947) 52.719,83.562 ccw(c52.733,83.947) 53.118,83.947 61.997,83.947 ; 52.515,85.495 ccw(c47.117,83.947) 52.392,85.874 cw(c52.247,86.231) 52.079,86.577 ccw(c47.117,83.947) 52.072,86.59 ccw(c51.879,86.923) 52.206,87.127 59.736,91.832 ; 52.664,80.998 60.595,76.781 ; 52.664,86.896 60.255,90.933 ccw(c60.595,91.113) 60.772,90.771 cw(c47.117,83.947) 61.325,89.528 cw(c61.461,89.168) 61.589,88.805 cw(c47.117,83.947) 62.048,87.121 ; 52.678,83.165 61.852,81.876 ; 52.678,84.729 61.852,86.018 ; 52.733,83.947 ccw(c47.117,83.947) 52.719,84.346 cw(c52.678,84.729) 52.611,85.108 ccw(c47.117,83.947) 52.608,85.121 ccw(c52.515,85.495) 52.885,85.601 ; 52.885,82.293 61.421,79.846 ; 52.885,85.601 61.421,88.048 ; 53.021,81.798 61.1,78.858 ccw(c61.461,78.726) 61.325,78.366 cw(c47.117,83.947) 60.772,77.123 cw(c60.595,76.781) 60.41,76.443 cw(c47.117,83.947) 59.467,74.974 ; 53.021,86.096 61.461,89.168 ; 53.262,82.641 62.048,80.773 ; 53.262,85.253 61.672,87.041 ccw(c62.048,87.121) 62.124,86.743 cw(c47.117,83.947) 62.313,85.396 cw(c62.345,85.012) 62.367,84.627 cw(c47.117,83.947) 62.345,82.882 ; 53.384,83.509 61.961,82.909 ccw(c62.345,82.882) 62.313,82.498 cw(c47.117,83.947) 62.124,81.151 cw(c62.048,80.773) 61.964,80.398 cw(c47.117,83.947) 61.461,78.726 ; 53.384,84.385 62.345,85.012 ; 68.755,73.079 ccw(c92.996,74.152) 68.897,71.323 ccw(c68.945,70.941) 68.999,70.56 ccw(c92.996,74.152) 69.241,69.204 cw(c69.323,68.828) 69.698,68.912 83.637,72.047 ; 68.755,75.226 83.412,74.577 ; 68.945,70.941 83.487,72.883 ; 68.945,77.364 ccw(c92.996,74.152) 68.775,75.61 ccw(c68.755,75.226) 68.741,74.841 ccw(c92.996,74.152) 68.741,73.464 cw(c68.755,73.079) 69.14,73.096 83.412,73.728 ; 69.116,74.152 84.07,74.152 ; 69.21,72.042 83.721,73.33 cw(c84.105,73.364) 84.079,73.748 cw(c92.996,74.152) 84.078,73.768 ccw(c84.07,74.152) 84.078,74.537 cw(c92.996,74.152) 84.105,74.941 ; 69.21,76.263 83.721,74.975 cw(c84.105,74.941) 84.147,75.324 cw(c92.996,74.152) 84.15,75.344 ccw(c84.209,75.724) 84.285,76.102 cw(c92.996,74.152) 84.382,76.495 ; 69.323,68.828 ccw(c92.996,74.152) 69.772,67.124 ccw(c69.886,66.756) 70.006,66.391 ccw(c92.996,74.152) 70.484,65.099 cw(c70.63,64.743) 70.985,64.892 84.154,70.432 ; 69.323,79.477 83.637,76.258 ; 69.489,69.948 84.209,72.581 ; 69.489,78.357 84.209,75.724 ; 69.886,66.756 83.859,71.228 ; 69.886,81.549 ccw(c92.996,74.152) 69.41,79.852 ccw(c69.323,79.477) 69.241,79.101 ccw(c92.996,74.152) 68.999,77.745 cw(c68.945,77.364) 69.326,77.313 83.487,75.422 ; 69.953,67.887 84.011,71.709 cw(c84.382,71.81) 84.29,72.184 cw(c92.996,74.152) 84.285,72.203 ccw(c84.209,72.581) 84.15,72.961 cw(c92.996,74.152) 84.105,73.364 ; 69.953,80.418 84.011,76.596 cw(c84.382,76.495) 84.491,76.864 cw(c92.996,74.152) 84.498,76.883 ccw(c84.623,77.247) 84.764,77.605 cw(c92.996,74.152) 84.929,77.975 ; 70.597,65.875 84.623,71.058 ; 70.597,82.43 84.623,77.247 ; 70.63,64.743 ccw(c92.996,74.152) 71.372,63.145 ccw(c71.549,62.803) 71.732,62.464 ccw(c92.996,74.152) 72.429,61.277 cw(c72.636,60.952) 72.959,61.161 84.947,68.933 ; 70.63,83.562 84.154,77.873 ; 71.416,63.928 84.582,70.165 cw(c84.929,70.33) 84.772,70.682 cw(c92.996,74.152) 84.764,70.7 ccw(c84.623,71.058) 84.498,71.422 cw(c92.996,74.152) 84.382,71.81 ; 71.416,84.377 84.582,78.14 cw(c84.929,77.975) 85.102,78.319 cw(c92.996,74.152) 85.111,78.337 ccw(c85.299,78.673) 85.501,79 cw(c92.996,74.152) 85.728,79.335 ; 71.549,62.803 84.517,69.665 ; 71.549,85.502 ccw(c92.996,74.152) 70.782,83.916 ccw(c70.63,83.562) 70.484,83.206 ccw(c92.996,74.152) 70.006,81.914 cw(c69.886,81.549) 70.253,81.431 83.859,77.077 ; 72.404,62.06 85.299,69.632 ; 72.404,86.245 85.299,78.673 ; 72.636,60.952 ccw(c92.996,74.152) 73.648,59.509 ccw(c73.883,59.204) 74.122,58.903 ccw(c92.996,74.152) 75.018,57.856 cw(c75.279,57.573) 75.56,57.836 85.991,67.598 ; 72.636,87.353 84.947,79.372 ; 73.554,60.288 85.415,68.746 ; 73.554,88.017 85.415,79.559 ; 73.883,59.204 85.44,68.242 ; 73.883,89.101 ccw(c92.996,74.152) 72.848,87.675 ccw(c72.636,87.353) 72.429,87.028 ccw(c92.996,74.152) 71.732,85.841 cw(c71.549,85.502) 71.89,85.322 84.517,78.64 ; 74.855,58.624 86.215,68.348 ; 74.855,89.681 86.215,79.957 ; 75.279,57.573 ccw(c92.996,74.152) 76.528,56.331 ccw(c76.813,56.072) 77.102,55.818 ccw(c92.996,74.152) 78.168,54.946 cw(c78.474,54.713) 78.705,55.021 87.255,66.467 ; 75.279,90.732 85.991,80.707 ; 76.298,57.081 86.485,67.496 cw(c86.754,67.771) 86.485,68.046 cw(c92.996,74.152) 86.472,68.061 ccw(c86.215,68.348) 85.971,68.645 ; 76.298,91.224 86.485,80.809 cw(c86.754,80.534) 87.035,80.797 cw(c92.996,74.152) 87.05,80.81 ccw(c87.343,81.061) 87.646,81.298 cw(c92.996,74.152) 87.976,81.533 ; 76.813,56.072 86.598,67.004 ; 76.813,92.233 ccw(c92.996,74.152) 75.544,91.011 ccw(c75.279,90.732) 75.018,90.448 ccw(c92.996,74.152) 74.122,89.402 cw(c73.883,89.101) 74.186,88.864 85.44,80.063 ; 77.873,55.672 87.343,67.244 ; 77.873,92.633 87.343,81.061 ; 78.392,22.431 89.886,23.065 ; 78.392,24.554 ccw(c97.628,23.493) 78.375,22.816 ccw(c78.392,22.431) 78.418,22.047 ccw(c97.628,23.493) 78.566,20.702 cw(c78.626,20.322) 79.006,20.385 89.98,22.216 ; 78.474,54.713 ccw(c92.996,74.152) 79.923,53.71 ccw(c80.249,53.505) 80.579,53.306 ccw(c92.996,74.152) 81.781,52.635 cw(c82.124,52.46) 82.296,52.804 88.698,65.576 ; 78.474,93.592 87.255,81.838 ; 78.626,20.322 ccw(c97.628,23.493) 78.989,18.622 ccw(c79.09,18.251) 79.199,17.881 ccw(c97.628,23.493) 79.638,16.601 cw(c79.779,16.243) 80.136,16.388 90.444,20.575 ; 78.626,26.664 89.98,24.769 ; 78.748,23.493 90.156,23.493 cw(c90.541,23.493) 90.551,23.877 cw(c97.628,23.493) 90.552,23.889 ccw(c90.584,24.272) 90.637,24.654 cw(c97.628,23.493) 90.713,25.042 ; 78.863,21.416 90.584,22.713 ; 78.863,25.57 90.584,24.272 ; 79.09,18.251 90.167,21.383 ; 79.09,28.735 ccw(c97.628,23.493) 78.693,27.043 ccw(c78.626,26.664) 78.566,26.283 ccw(c97.628,23.493) 78.418,24.938 cw(c78.392,24.554) 78.777,24.533 89.886,23.92 ; 79.205,19.364 90.337,21.859 cw(c90.713,21.943) 90.639,22.321 cw(c97.628,23.493) 90.637,22.332 ccw(c90.584,22.713) 90.552,23.097 cw(c97.628,23.493) 90.541,23.493 ; 79.205,27.621 90.337,25.127 cw(c90.713,25.042) 90.807,25.416 cw(c97.628,23.493) 90.81,25.427 ccw(c90.925,25.794) 91.06,26.154 cw(c97.628,23.493) 91.219,26.517 ; 79.565,54.408 87.759,66.453 cw(c87.976,66.772) 87.662,66.995 cw(c92.996,74.152) 87.646,67.007 ccw(c87.343,67.244) 87.05,67.494 cw(c92.996,74.152) 86.754,67.771 ; 79.565,93.897 87.759,81.852 cw(c87.976,81.533) 88.298,81.743 cw(c92.996,74.152) 88.315,81.753 ccw(c88.648,81.948) 88.988,82.128 cw(c92.996,74.152) 89.354,82.302 ; 79.771,17.362 90.925,21.191 ; 79.771,29.623 90.925,25.794 ; 79.779,16.243 ccw(c97.628,23.493) 80.505,14.664 ccw(c80.685,14.324) 80.872,13.987 ccw(c97.628,23.493) 81.58,12.834 cw(c81.797,12.515) 82.113,12.735 91.256,19.074 ; 79.779,30.742 90.444,26.411 ; 80.249,53.505 87.957,65.989 ; 80.249,94.8 ccw(c92.996,74.152) 78.785,93.82 ccw(c78.474,93.592) 78.168,93.359 ccw(c92.996,74.152) 77.102,92.487 cw(c76.813,92.233) 77.07,91.946 86.598,81.301 ; 80.554,15.435 90.871,20.304 cw(c91.219,20.468) 91.064,20.82 cw(c97.628,23.493) 91.06,20.831 ccw(c90.925,21.191) 90.81,21.559 cw(c97.628,23.493) 90.713,21.943 ; 80.554,31.55 90.871,26.682 cw(c91.219,26.517) 91.393,26.861 cw(c97.628,23.493) 91.398,26.871 ccw(c91.59,27.204) 91.801,27.526 cw(c97.628,23.493) 92.035,27.846 ; 80.685,14.324 90.809,19.802 ; 80.685,32.662 ccw(c97.628,23.493) 79.928,31.097 ccw(c79.779,30.742) 79.638,30.384 ccw(c97.628,23.493) 79.199,29.104 cw(c79.09,28.735) 79.461,28.63 90.167,25.603 ; 81.363,53.298 88.648,66.357 ; 81.363,95.007 88.648,81.948 ; 81.544,13.606 91.59,19.781 ; 81.544,33.38 91.59,27.204 ; 81.797,12.515 ccw(c97.628,23.493) 82.85,11.133 ccw(c83.1,10.84) 83.356,10.553 ccw(c97.628,23.493) 84.3,9.582 cw(c84.58,9.319) 84.841,9.602 92.377,17.788 ; 81.797,34.47 91.256,27.911 ; 82.124,52.46 ccw(c92.996,74.152) 83.727,51.728 ccw(c84.084,51.584) 84.443,51.445 ccw(c92.996,74.152) 85.745,50.996 cw(c86.113,50.884) 86.222,51.253 90.275,64.953 ; 82.124,95.845 88.698,82.729 ; 82.729,11.896 91.732,18.903 cw(c92.035,19.14) 91.807,19.45 cw(c97.628,23.493) 91.801,19.459 ccw(c91.59,19.781) 91.398,20.115 cw(c97.628,23.493) 91.219,20.468 ; 82.729,35.089 91.732,28.082 cw(c92.035,27.846) 92.28,28.143 cw(c97.628,23.493) 92.287,28.151 ccw(c92.548,28.435) 92.824,28.703 cw(c97.628,23.493) 93.123,28.963 ; 83.1,10.84 91.781,18.4 ; 83.1,36.145 ccw(c97.628,23.493) 82.019,34.784 ccw(c81.797,34.47) 81.58,34.151 ccw(c97.628,23.493) 80.872,32.999 cw(c80.685,32.662) 81.024,32.479 90.809,27.183 ; 83.251,52.351 89.196,65.652 cw(c89.354,66.003) 89.006,66.168 cw(c92.996,74.152) 88.988,66.177 ccw(c88.648,66.357) 88.315,66.552 cw(c92.996,74.152) 87.976,66.772 ; 83.251,95.954 89.196,82.653 cw(c89.354,82.302) 89.708,82.451 cw(c92.996,74.152) 89.727,82.459 ccw(c90.088,82.592) 90.455,82.71 cw(c92.996,74.152) 90.845,82.816 ; 84.084,51.584 89.473,65.23 ; 84.084,96.721 ccw(c92.996,74.152) 82.47,96.015 ccw(c82.124,95.845) 81.781,95.67 ccw(c92.996,74.152) 80.579,94.999 cw(c80.249,94.8) 80.452,94.472 87.957,82.316 ; 84.095,10.328 92.548,18.551 ; 84.095,36.658 92.548,28.435 ; 84.58,9.319 ccw(c97.628,23.493) 85.911,8.201 ccw(c86.219,7.97) 86.531,7.745 ccw(c97.628,23.493) 87.664,7.004 cw(c87.996,6.809) 88.188,7.142 93.751,16.777 ; 84.58,37.666 92.377,29.197 ; 84.929,70.33 ccw(c92.996,74.152) 85.111,69.968 cw(c85.299,69.632) 85.501,69.305 ccw(c92.996,74.152) 85.512,69.288 ccw(c85.728,68.97) 85.415,68.746 ; 85.216,51.575 90.088,65.713 ; 85.216,96.73 90.088,82.592 ; 85.415,79.559 cw(c85.728,79.335) 85.959,79.644 cw(c92.996,74.152) 85.971,79.66 ccw(c86.215,79.957) 86.472,80.244 cw(c92.996,74.152) 86.754,80.534 ; 85.626,8.919 92.878,17.725 ; 85.626,38.066 92.878,29.261 cw(c93.123,28.963) 93.426,29.2 cw(c97.628,23.493) 93.435,29.207 ccw(c93.752,29.426) 94.08,29.628 cw(c97.628,23.493) 94.428,29.816 ; 85.728,68.97 ccw(c92.996,74.152) 85.971,68.645 ; 86.113,50.884 ccw(c92.996,74.152) 87.82,50.446 ccw(c88.197,50.367) 88.575,50.294 ccw(c92.996,74.152) 89.935,50.081 cw(c90.318,50.036) 90.36,50.418 91.937,64.618 ; 86.113,97.421 90.275,83.352 ; 86.219,7.97 93.036,17.245 ; 86.219,39.016 ccw(c97.628,23.493) 84.866,37.924 ccw(c84.58,37.666) 84.3,37.403 ccw(c97.628,23.493) 83.356,36.433 cw(c83.1,36.145) 83.391,35.892 91.781,28.585 ; 87.242,50.976 90.753,65.115 cw(c90.845,65.489) 90.474,65.59 cw(c92.996,74.152) 90.455,65.595 ccw(c90.088,65.713) 89.727,65.846 cw(c92.996,74.152) 89.354,66.003 ; 87.242,97.329 90.753,83.19 cw(c90.845,82.816) 91.221,82.901 cw(c92.996,74.152) 91.24,82.905 ccw(c91.619,82.972) 92.001,83.023 cw(c92.996,74.152) 92.404,83.059 ; 87.302,7.687 93.752,17.559 ; 87.302,39.298 93.752,29.426 ; 87.996,6.809 ccw(c97.628,23.493) 89.539,6.008 ccw(c89.89,5.85) 90.244,5.699 ccw(c97.628,23.493) 91.511,5.225 cw(c91.877,5.106) 91.992,5.473 95.314,16.092 ; 87.996,40.177 93.751,30.208 ; 88.197,50.367 91.099,64.749 ; 88.197,97.938 ccw(c92.996,74.152) 86.483,97.527 ccw(c86.113,97.421) 85.745,97.309 ccw(c92.996,74.152) 84.443,96.86 cw(c84.084,96.721) 84.225,96.363 89.473,83.075 ; 89.103,6.647 94.254,16.826 cw(c94.428,17.169) 94.089,17.352 cw(c97.628,23.493) 94.08,17.358 ccw(c93.752,17.559) 93.435,17.779 cw(c97.628,23.493) 93.123,18.022 ; 89.103,40.338 94.254,30.16 cw(c94.428,29.816) 94.776,29.981 cw(c97.628,23.493) 94.786,29.985 ccw(c95.143,30.13) 95.507,30.255 cw(c97.628,23.493) 95.888,30.363 ; 89.313,50.558 91.619,65.333 ; 89.313,97.747 91.619,82.972 ; 89.89,5.85 94.513,16.392 ; 89.89,41.135 ccw(c97.628,23.493) 88.331,40.366 ccw(c87.996,40.177) 87.664,39.981 ccw(c97.628,23.493) 86.531,39.241 cw(c86.219,39.016) 86.447,38.705 93.036,29.741 ; 90.318,50.036 ccw(c92.996,74.152) 92.075,49.905 ccw(c92.46,49.893) 92.844,49.888 ccw(c92.996,74.152) 94.221,49.918 cw(c94.606,49.941) 94.58,50.325 93.633,64.58 ; 90.318,98.269 91.937,83.687 ; 90.845,65.489 ccw(c92.996,74.152) 91.24,65.4 cw(c91.619,65.333) 92.001,65.282 ccw(c92.996,74.152) 92.021,65.279 ccw(c92.404,65.246) 92.379,64.861 91.413,50.325 ; 91.008,5.811 95.143,16.855 ; 91.008,41.174 95.143,30.13 ; 91.099,83.556 88.273,97.561 ccw(c88.197,97.938) 88.575,98.011 cw(c92.996,74.152) 89.935,98.224 cw(c90.318,98.269) 90.701,98.309 cw(c92.996,74.152) 92.46,98.412 ; 91.413,97.98 92.379,83.444 cw(c92.404,83.059) 92.789,83.077 cw(c92.996,74.152) 92.809,83.077 ccw(c93.194,83.077) 93.578,83.06 cw(c92.996,74.152) 93.982,83.025 ; 91.877,5.106 ccw(c97.628,23.493) 93.558,4.663 ccw(c93.935,4.585) 94.313,4.515 ccw(c97.628,23.493) 95.654,4.329 cw(c96.037,4.293) 96.069,4.677 96.988,15.765 ; 91.877,41.879 95.314,30.893 ; 92.035,19.14 ccw(c97.628,23.493) 92.287,18.834 cw(c92.548,18.551) 92.824,18.282 ccw(c97.628,23.493) 92.832,18.275 ccw(c93.123,18.022) 92.878,17.725 ; 92.404,65.246 ccw(c92.996,74.152) 92.809,65.228 cw(c93.194,65.228) 93.578,65.245 ccw(c92.996,74.152) 93.598,65.246 ccw(c93.982,65.28) 94.024,64.898 95.633,50.418 ; 92.46,49.893 92.784,64.561 ; 92.784,83.744 92.468,98.027 ccw(c92.46,98.412) 92.844,98.417 cw(c92.996,74.152) 94.221,98.387 cw(c94.606,98.364) 94.99,98.335 cw(c92.996,74.152) 96.739,98.127 ; 92.993,5.19 95.794,16.249 cw(c95.888,16.622) 95.518,16.727 cw(c97.628,23.493) 95.507,16.73 ccw(c95.143,16.855) 94.786,17 cw(c97.628,23.493) 94.428,17.169 ; 92.993,41.795 95.794,30.736 cw(c95.888,30.363) 96.264,30.447 cw(c97.628,23.493) 96.275,30.449 ccw(c96.655,30.513) 97.037,30.555 cw(c97.628,23.493) 97.433,30.577 ; 93.194,65.228 93.525,50.278 ; 93.194,83.077 93.525,98.027 ; 93.633,83.725 94.606,98.364 ; 93.935,4.585 96.142,15.882 ; 93.935,42.4 ccw(c97.628,23.493) 92.246,41.991 ccw(c91.877,41.879) 91.511,41.761 ccw(c97.628,23.493) 90.244,41.286 cw(c89.89,41.135) 90.044,40.782 94.513,30.594 ; 93.982,65.28 ccw(c92.996,74.152) 94.383,65.334 cw(c94.762,65.402) 95.138,65.487 ccw(c92.996,74.152) 95.157,65.491 ccw(c95.528,65.593) 95.638,65.223 99.77,51.253 ; 94.476,64.674 96.739,50.178 ; 94.476,83.631 96.68,97.747 ccw(c96.739,98.127) 97.119,98.065 cw(c92.996,74.152) 98.469,97.792 cw(c98.843,97.702) 99.216,97.607 cw(c92.996,74.152) 100.902,97.094 ; 94.606,49.941 ccw(c92.996,74.152) 96.358,50.122 ccw(c96.739,50.178) 97.119,50.24 ccw(c92.996,74.152) 98.469,50.513 cw(c98.843,50.602) 98.751,50.976 95.308,64.842 ; 94.762,65.402 97.72,50.744 ; 94.762,82.903 97.72,97.561 ; 95.035,4.792 96.655,16.473 ; 95.035,42.194 96.655,30.513 ; 95.308,83.463 98.843,97.702 ; 95.528,65.593 ccw(c92.996,74.152) 95.914,65.716 cw(c96.275,65.85) 96.63,65.999 ccw(c92.996,74.152) 96.648,66.007 ccw(c96.996,66.172) 97.169,65.828 103.696,52.804 ; 95.528,82.712 ccw(c92.996,74.152) 95.138,82.818 cw(c94.762,82.903) 94.383,82.971 ccw(c92.996,74.152) 94.363,82.974 ccw(c93.982,83.025) 94.024,83.407 95.633,97.887 ; 95.888,16.622 ccw(c97.628,23.493) 96.275,16.536 cw(c96.655,16.473) 97.037,16.43 ccw(c97.628,23.493) 97.049,16.429 ccw(c97.433,16.408) 97.422,16.023 97.108,4.62 ; 96.037,4.293 ccw(c97.628,23.493) 97.774,4.228 ccw(c98.159,4.235) 98.544,4.249 ccw(c97.628,23.493) 99.892,4.361 cw(c100.274,4.41) 100.221,4.792 98.693,15.812 ; 96.037,42.692 96.988,31.22 ; 96.122,65.082 100.902,51.211 ; 96.122,83.222 100.776,96.73 ccw(c100.902,97.094) 101.265,96.965 cw(c92.996,74.152) 102.546,96.459 cw(c102.898,96.305) 103.249,96.145 cw(c92.996,74.152) 104.818,95.343 ; 96.142,31.103 94.009,42.022 ccw(c93.935,42.4) 94.313,42.47 cw(c97.628,23.493) 95.654,42.656 cw(c96.037,42.692) 96.421,42.72 cw(c97.628,23.493) 98.159,42.75 ; 96.275,65.85 101.767,51.942 ; 96.275,82.455 101.767,96.363 ; 96.911,65.394 102.741,52.351 ccw(c102.898,52) 102.546,51.846 cw(c92.996,74.152) 101.265,51.34 cw(c100.902,51.211) 100.537,51.089 cw(c92.996,74.152) 98.843,50.602 ; 96.911,82.911 102.898,96.305 ; 96.996,66.172 ccw(c92.996,74.152) 97.354,66.362 cw(c97.686,66.557) 98.009,66.766 ccw(c92.996,74.152) 98.025,66.777 ccw(c98.339,67.001) 98.569,66.693 107.288,55.021 ; 96.996,82.133 ccw(c92.996,74.152) 96.63,82.306 cw(c96.275,82.455) 95.914,82.589 ccw(c92.996,74.152) 95.895,82.595 ccw(c95.528,82.712) 95.638,83.082 99.77,97.052 ; 97.108,42.365 97.422,30.962 ; 97.422,30.962 cw(c97.433,30.577) 97.818,30.577 cw(c97.628,23.493) 97.829,30.577 ccw(c98.213,30.556) 98.596,30.513 cw(c97.628,23.493) 98.987,30.448 ; 97.433,16.408 ccw(c97.628,23.493) 97.829,16.408 cw(c98.213,16.43) 98.596,16.472 ccw(c97.628,23.493) 98.607,16.473 ccw(c98.987,16.537) 99.061,16.159 101.248,4.963 ; 97.67,65.774 104.818,52.962 ; 97.67,82.53 104.63,95.007 ccw(c104.818,95.343) 105.152,95.153 cw(c92.996,74.152) 106.324,94.43 cw(c106.644,94.216) 106.961,93.996 cw(c92.996,74.152) 108.364,92.931 ; 97.686,66.557 105.541,53.833 ; 97.686,81.748 105.541,94.472 ; 97.842,15.742 98.159,4.235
